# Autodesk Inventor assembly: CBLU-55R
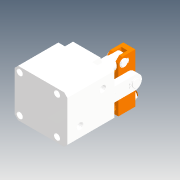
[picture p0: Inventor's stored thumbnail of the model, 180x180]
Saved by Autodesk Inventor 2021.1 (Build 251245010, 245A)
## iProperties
Created: 2019-05
Part Number: CBLU-55R
Description: STEP AP214
Document SubType Name: Assembly
Designer: user
Title: CBLU-55R.STEP
Revision Number: ÈÎºÎ
Sending System: SolidWorks 2016
Preprocessor: SwSTEP 2.0
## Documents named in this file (11)
- D:\Vault_2016\Projekty\Clamptek\Hydraulic\CBLU\CBLU-55\Inventor\CBLU-55R\CBLU-55R.iam
- D:\Vault_2016\Projekty\Clamptek\Hydraulic\CBLU\CBLU-55\Inventor\CBLU-55R\CBLU-55CR±¾Ìå_1_1.ipt
- D:\Vault_2016\Projekty\Clamptek\Hydraulic\CBLU\CBLU-55\Inventor\CBLU-55R\changxiao.ipt
- D:\Vault_2016\Projekty\Clamptek\Hydraulic\CBLU\CBLU-55\Inventor\CBLU-55R\duanxiao.ipt
- D:\Vault_2016\Projekty\Clamptek\Hydraulic\CBLU\CBLU-55\Inventor\CBLU-55R\huosaigan_3_1.ipt
- D:\Vault_2016\Projekty\Clamptek\Hydraulic\CBLU\CBLU-55\Inventor\CBLU-55R\kahuang.ipt
- D:\Vault_2016\Projekty\Clamptek\Hydraulic\CBLU\CBLU-55\Inventor\CBLU-55R\kahuang01.ipt
- D:\Vault_2016\Projekty\Clamptek\Hydraulic\CBLU\CBLU-55\Inventor\CBLU-55R\liangan.ipt
- D:\Vault_2016\Projekty\Clamptek\Hydraulic\CBLU\CBLU-55\Inventor\CBLU-55R\luogan.ipt
- D:\Vault_2016\Projekty\Clamptek\Hydraulic\CBLU\CBLU-55\Inventor\CBLU-55R\luomu.ipt
- D:\Vault_2016\Projekty\Clamptek\Hydraulic\CBLU\CBLU-55\Inventor\CBLU-55R\yabi.ipt
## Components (16 placed, 16 different names)
1. CBLU-55CR±¾Ìå_1_1_1
2. changxiao_2
3. duanxiao_3
4. huosaigan_3_1_4
5. kahuang_5
6. kahuang01_6
7. liangan_7
8. luogan_8
9. luomu_9
10. yabi_10
11. liangan_11
12. changxiao_12
13. kahuang_13
14. kahuang01_14
15. kahuang_15
16. kahuang_16
